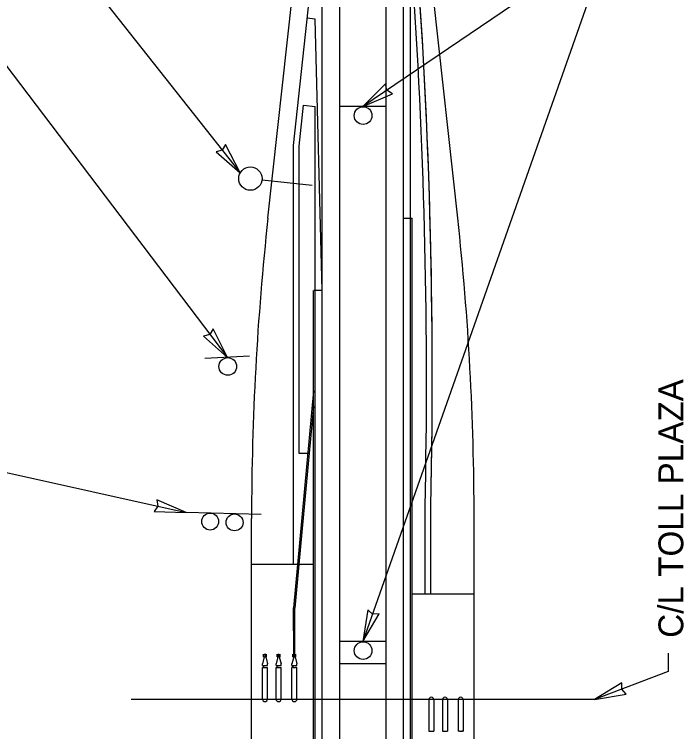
# Model space of a CAD drawing. Extents: x -102643 to -98250, y 54554 to 62384.
# Drawn here: x -101032 to -100108, y 56510 to 57501 of the extents above; entities that cross this region are included whole.
import ezdxf

# ---------------------------------------------------------------- set-up
doc = ezdxf.new("R2010")
doc.units = 0
for name, color, linetype in [('Default', 7, 'Continuous'), ('LeaderLine_dp', 7, 'Continuous'), ('RoadwayMisc', 7, 'Continuous'), ('SignCantilever', 7, 'Continuous'), ('SignSupport', 7, 'Continuous'), ('TextLabel', 7, 'Continuous')]:
    doc.layers.add(name, color=color, linetype=linetype)

msp = doc.modelspace()

# ---------------------------------------------------------------- linework, layer by layer
at = {"layer": 'Default'}
msp.add_line((-100230.78, 56554.62), (-100870.78, 56554.62), dxfattribs=at)
at = {"layer": 'LeaderLine_dp'}
for p, q in [((-101212.67, 57905.28), (-100720.22, 57282.08)), ((-100209.35, 57605.31), (-100550.73, 56634.83)), ((-100209.35, 57605.31), (-100550.73, 57373.9)), ((-101108.2, 57515.43), (-100737.95, 57026.88)), ((-100519.27, 57405.02), (-100550.73, 57373.9)), ((-100517.45, 57396.46), (-100519.27, 57405.02)), ((-100550.73, 57373.9), (-100510.01, 57391.36)), ((-100510.01, 57391.36), (-100517.45, 57396.46)), ((-100740.6, 57321.42), (-100745.15, 57313.63)), ((-100720.22, 57282.08), (-100740.6, 57321.42)), ((-100745.15, 57313.63), (-100753.55, 57311.19)), ((-100753.55, 57311.19), (-100720.22, 57282.08)), ((-100757.67, 57066.55), (-100762.35, 57058.83)), ((-100737.95, 57026.88), (-100757.67, 57066.55)), ((-100762.35, 57058.83), (-100770.79, 57056.54)), ((-100770.79, 57056.54), (-100737.95, 57026.88)), ((-101214.84, 56906.72), (-100794.86, 56812.93)), ((-100794.86, 56812.93), (-100835.48, 56830.61)), ((-100835.48, 56830.61), (-100834.09, 56821.69)), ((-100834.09, 56821.69), (-100839.08, 56814.51)), ((-100839.08, 56814.51), (-100794.86, 56812.93)), ((-100543.94, 56678.55), (-100550.73, 56634.83)), ((-100537.39, 56672.75), (-100543.94, 56678.55)), ((-100550.73, 56634.83), (-100528.37, 56673.08)), ((-100528.37, 56673.08), (-100537.39, 56672.75)), ((-100129.18, 56618.87), (-100129.18, 56593.2)), ((-100129.18, 56593.2), (-100230.78, 56554.62)), ((-100192.99, 56577.64), (-100230.78, 56554.62)), ((-100193.2, 56568.89), (-100192.99, 56577.64)), ((-100187.13, 56562.21), (-100193.2, 56568.89)), ((-100230.78, 56554.62), (-100187.13, 56562.21))]:
    msp.add_line(p, q, dxfattribs=at)
at = {"layer": 'RoadwayMisc'}
for p, q in [((-100582.78, 55117.42), (-100582.78, 62374.01)), ((-100518.78, 55119.1), (-100518.78, 62374.01)), ((-100494.78, 55409.74), (-100494.78, 57849.73)), ((-100646.71, 57320.05), (-100606.78, 57685.42)), ((-100606.78, 57119.62), (-100606.78, 57685.42)), ((-100681.83, 57219.61), (-100641.39, 57589.63)), ((-100419.73, 57219.61), (-100460.17, 57589.63)), ((-100484.78, 57219.62), (-100484.78, 57542.62)), ((-100616.78, 57494.59), (-100627.51, 57495.74)), ((-100606.78, 57119.62), (-100616.78, 57494.59)), ((-100638.76, 57319.18), (-100632.59, 57375.6)), ((-100632.59, 57375.6), (-100616.78, 57373.9)), ((-100616.78, 57119.62), (-100616.78, 57373.9)), ((-100646.71, 56741.25), (-100646.71, 57320.05)), ((-100638.71, 56894.62), (-100638.71, 57320.05)), ((-100494.78, 57219.63), (-100484.78, 57219.62)), ((-100484.78, 57219.63), (-100482.78, 57219.63)), ((-100484.78, 55939.63), (-100484.78, 57219.63)), ((-100482.78, 55689.04), (-100482.78, 57219.63)), ((-100618.79, 56019.62), (-100618.79, 57119.63)), ((-100616.69, 57119.63), (-100618.69, 57119.63)), ((-100616.78, 56019.62), (-100616.79, 57119.62)), ((-100606.78, 57119.63), (-100615.69, 57119.63)), ((-100606.78, 56019.62), (-100606.78, 57119.63)), ((-100618.79, 56981.12), (-100641.14, 56741.01)), ((-100618.79, 56959.55), (-100639.13, 56741.01)), ((-100626.84, 56894.62), (-100638.71, 56894.62)), ((-100464.78, 56700.68), (-100464.77, 56821.18)), ((-100456.78, 56700.68), (-100456.77, 56821.18)), ((-100704.44, 56486.13), (-100704.44, 56804.62)), ((-100397.12, 56304.62), (-100397.12, 56804.62)), ((-100641.14, 56741.01), (-100704.44, 56741.01)), ((-100641.14, 56741.01), (-100646.71, 56681.13)), ((-100639.13, 56741.01), (-100644.71, 56681.03)), ((-100618.79, 56741.01), (-100639.13, 56741.01)), ((-100482.78, 56700.59), (-100397.12, 56700.59)), ((-100646.19, 56617.23), (-100646.71, 56681.13)), ((-100644.69, 56617.56), (-100644.71, 56681.03)), ((-100686.97, 56613.77), (-100689.38, 56603.77)), ((-100687.97, 56613.77), (-100687.97, 56617.26)), ((-100687.97, 56613.77), (-100686.97, 56613.77)), ((-100686.97, 56613.77), (-100686.97, 56617.26)), ((-100686.97, 56617.26), (-100684.97, 56617.26)), ((-100686.97, 56613.77), (-100684.97, 56613.77)), ((-100684.97, 56613.77), (-100684.97, 56617.26)), ((-100684.97, 56613.77), (-100682.55, 56603.77)), ((-100683.97, 56613.77), (-100684.97, 56613.77)), ((-100683.97, 56613.77), (-100683.97, 56617.26)), ((-100668.14, 56613.77), (-100670.56, 56603.77)), ((-100669.14, 56613.77), (-100669.14, 56617.26)), ((-100669.14, 56613.77), (-100668.14, 56613.77)), ((-100668.14, 56613.77), (-100668.14, 56617.26)), ((-100668.14, 56617.26), (-100666.14, 56617.26)), ((-100668.14, 56613.77), (-100666.14, 56613.77)), ((-100666.14, 56613.77), (-100666.14, 56617.26)), ((-100666.14, 56613.77), (-100663.73, 56603.77)), ((-100665.14, 56613.77), (-100666.14, 56613.77)), ((-100665.14, 56613.77), (-100665.14, 56617.26)), ((-100646.32, 56613.77), (-100648.73, 56603.77)), ((-100647.32, 56613.77), (-100647.32, 56617.26)), ((-100647.32, 56613.77), (-100646.32, 56613.77)), ((-100646.32, 56613.77), (-100646.32, 56617.26)), ((-100646.32, 56617.26), (-100644.32, 56617.26)), ((-100646.32, 56613.77), (-100644.32, 56613.77)), ((-100644.32, 56613.77), (-100644.32, 56617.26)), ((-100643.32, 56613.77), (-100644.32, 56613.77)), ((-100644.32, 56613.77), (-100641.9, 56603.77)), ((-100643.32, 56613.77), (-100643.32, 56617.26)), ((-100689.39, 56598.77), (-100682.56, 56598.77)), ((-100689.39, 56555.12), (-100689.39, 56598.77)), ((-100689.38, 56601.77), (-100689.38, 56603.77)), ((-100689.38, 56601.77), (-100682.55, 56601.77)), ((-100688.58, 56601.19), (-100687.58, 56601.19)), ((-100688.58, 56600.19), (-100688.58, 56601.19)), ((-100687.58, 56600.19), (-100688.58, 56600.19)), ((-100687.58, 56601.19), (-100687.58, 56600.19)), ((-100682.56, 56555.12), (-100682.56, 56598.77)), ((-100682.55, 56601.77), (-100682.55, 56603.77)), ((-100670.56, 56601.77), (-100670.56, 56603.77)), ((-100670.56, 56601.77), (-100663.73, 56601.77)), ((-100670.56, 56555.12), (-100670.56, 56598.77)), ((-100670.56, 56598.77), (-100663.73, 56598.77)), ((-100669.76, 56601.19), (-100668.76, 56601.19)), ((-100669.76, 56600.19), (-100669.76, 56601.19)), ((-100668.76, 56600.19), (-100669.76, 56600.19)), ((-100668.76, 56601.19), (-100668.76, 56600.19)), ((-100663.73, 56601.77), (-100663.73, 56603.77)), ((-100663.73, 56555.12), (-100663.73, 56598.77)), ((-100648.74, 56555.12), (-100648.74, 56598.77)), ((-100647.98, 56598.77), (-100648.74, 56598.77)), ((-100648.73, 56601.77), (-100648.73, 56603.77)), ((-100648.73, 56601.77), (-100641.9, 56601.77)), ((-100646.98, 56598.77), (-100647.98, 56598.77)), ((-100647.93, 56601.19), (-100646.93, 56601.19)), ((-100647.93, 56600.19), (-100647.93, 56601.19)), ((-100646.93, 56600.19), (-100647.93, 56600.19)), ((-100646.98, 56598.77), (-100643.65, 56598.77)), ((-100646.93, 56601.19), (-100646.93, 56600.19)), ((-100643.65, 56598.69), (-100643.82, 56598.69)), ((-100642.65, 56598.77), (-100643.65, 56598.77)), ((-100642.65, 56598.77), (-100641.91, 56598.77)), ((-100641.91, 56555.12), (-100641.91, 56598.77)), ((-100641.9, 56601.77), (-100641.9, 56603.77)), ((-100582.78, 56604.62), (-100518.78, 56604.62)), ((-100459.65, 56554.62), (-100459.65, 56510.97)), ((-100452.82, 56554.62), (-100452.82, 56510.98)), ((-100440.82, 56554.62), (-100440.82, 56510.98)), ((-100433.99, 56554.62), (-100433.99, 56510.98)), ((-100419, 56554.62), (-100419, 56510.98)), ((-100412.17, 56554.62), (-100412.17, 56510.98)), ((-100459.65, 56510.97), (-100452.82, 56510.98)), ((-100440.82, 56510.98), (-100433.99, 56510.98)), ((-100418.24, 56510.98), (-100419, 56510.98)), ((-100417.24, 56510.98), (-100418.24, 56510.98)), ((-100417.24, 56510.98), (-100413.91, 56510.98)), ((-100413.91, 56511.06), (-100414.08, 56511.06)), ((-100412.91, 56510.98), (-100413.91, 56510.98)), ((-100412.91, 56510.98), (-100412.17, 56510.98))]:
    msp.add_line(p, q, dxfattribs=at)
for centre, radius, start, end in [((-108454.83, 56997.32), 8000, 358.738391, 5.072322), ((-108454.83, 56997.32), 8000, 358.738391, 4.896535), ((-108454.83, 56997.32), 7992, 358.738391, 3.912422), ((-96884.72, 56804.62), 3819.72, 173.76281, 179.99998), ((-104216.84, 56804.63), 3819.72, 359.99998, 6.23715), ((-100685.97, 56555.29), 3.42, 180.00001, 0.00001), ((-100667.15, 56555.29), 3.42, 180.00001, 0.00001), ((-100645.32, 56555.29), 3.42, 180.00001, 0.00001), ((-100456.23, 56554.46), 3.42, 0.00001, 180.00001), ((-100437.41, 56554.46), 3.42, 0.00001, 180.00001), ((-100415.58, 56554.46), 3.42, 0.00001, 180.00001)]:
    msp.add_arc(centre, radius, start, end, dxfattribs=at)
at = {"layer": 'SignCantilever'}
msp.add_line((-100620.65, 57264.54), (-100689.64, 57272.09), dxfattribs=at)
msp.add_circle((-100706.13, 57274.19), 16.16, dxfattribs=at)
at = {"layer": 'SignSupport'}
for p, q in [((-100519.87, 57373.9), (-100581.59, 57373.9)), ((-100707.48, 57028.89), (-100769.11, 57025.66)), ((-100691.29, 56810.44), (-100794.86, 56812.93)), ((-100519.87, 56634.83), (-100581.59, 56634.83))]:
    msp.add_line(p, q, dxfattribs=at)
for centre, radius in [((-100550.41, 57361.28), 12.21), ((-100737.31, 57014.69), 12.21), ((-100761.6, 56800.49), 11.67), ((-100727.94, 56799.35), 11.67), ((-100550.41, 56622.21), 12.21)]:
    msp.add_circle(centre, radius, dxfattribs=at)

# ---------------------------------------------------------------- texts
at = {"layer": 'TextLabel'}
msp.add_text('C/L TOLL PLAZA', height=34.335, rotation=90, dxfattribs=at).set_placement((-100108.16, 56639.92))

doc.saveas('drawing.dxf')
